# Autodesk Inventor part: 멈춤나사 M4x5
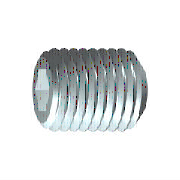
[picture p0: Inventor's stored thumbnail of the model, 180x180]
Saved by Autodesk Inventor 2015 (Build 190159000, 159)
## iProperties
IsCustomPart: 1
Created: 2012-02
Part Number: 멈춤나사 M4x5
Material: 강철, 연강
Description: 6각 소켓 머리 없는 멈춤 나사
Document SubType Name: Modeling
Standard: KS B 1028
Designer: mduedu
Standards Organization: KS
Language: ko-KR
Size Designation: 납작점M4x5
Categories: <MemberInstance><Categories><Category DisplayName="조임쇠" InternalName="e4da775c-781d-43d5-af7c-5136215cf5a6" Mnemonic="FSTN"><Category DisplayName="볼트" InternalN
Density: 1 g/cm^3
Appearance: 강철
Author: mduedu
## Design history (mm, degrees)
sketch "스케치1"
  geometry: L1 (0, 0)-(1.833, 0); L2 (5, 1.155)-(5, 2); L3 (5, 2)-(0, 2); L4 (5, 1.155)-(2.5, 1.155); L5 (2.5, 1.155)-(1.833, 0); L6 (0, -0.4)-(0, 2.4) reference; L7 (0, 2)-(0, 0)
  constraints: 13 end point, 3 parallel, 1 collinear, 1 perpendicular, 1 point on line
  dimensions: "d0" = 2.5 distance of L2.start L4.end (= INTI); "d1" = 60 deg angle of L5 L1; "d2" = 4 diameter of L3 L1 (= NND); "d3" = 2.3094 diameter of L4 L1 (= 1.1547 x SW); "d5" = 5 distance from line of L2 L3.end (= NLG)
revolve "본체" sketch "스케치1" stored, may be unused: angle "d6" = 90 deg
sketch "스케치2"
  geometry: L1 (-0.577, 1)-(0.577, 1); L2 (0.577, 1)-(1.155, 0); L3 (1.155, 0)-(0.577, -1); L4 (0.577, -1)-(-0.577, -1); L5 (-0.577, -1)-(-1.155, 0); L6 (-1.155, 0)-(-0.577, 1); A1 r 1.155 centre (0, 0) between (-0.577, 1) and (0.577, 1) reference; 2 further points
  constraints: 12 end point, 2 point on circle, 1 coincident, 1 horizontal, 11 other
extrude "슬롯" join sketch "스케치2" taper "d9" = 0 deg; stored distance "d21" = 10
workaxis "Work Axis1"
workplane "Work Plane1"
body "Solid1"
chamfer "모따기1" distance "d7" = 0.42941 (= -0.5 x GD1 + 0.5 x NND); stored, may be unused: angle "d8" = 45 deg (= FAWI), second distance "d29" = 0.42941 (= -0.5 x GD1 + 0.5 x NND)
feature "스레드" dims "d11" = 5 (= NLG), "d12" = 0
chamfer "모따기2" distance "d13" = 0.42941 (= -0.5 x GD1 + 0.5 x NND); stored, may be unused: angle "d14" = 45 deg (= FAWI), second distance "d30" = 0.42941 (= -0.5 x GD1 + 0.5 x NND)
other parameters: "NND" = 4 [user parameter; used in 5 equation terms], "NLG" = 5 [user parameter; used in 2 equation terms], "INTI" = 2.5 [user parameter; used in 1 equation term], "FAWI" = 45 deg [user parameter; used in 2 equation terms], "SW" = 2 [user parameter; used in 2 equation terms], "GD1" = 3.14117 (= THREADDIA - 1.2269 x PTC) [user parameter; used in 4 equation terms], "d4" = 0, "FAWI1" = 45 deg [user parameter], "d15" = 0, "d31" = 0, "GUL" = 0.42941 (= 0.61345 x PTC) [user parameter], "SPD" = 2.5 [user parameter], "TPU" = 14.28571 (computed from PTC) [user parameter], "TOA" = 30 deg [user parameter], "THREADDIA" = 4 [user parameter; used in 1 equation term], "PTC" = 0.7 [user parameter; used in 4 equation terms], "GAL" = 0.42941 (= 0.61345 x PTC) [user parameter], "E0" = 2.31 (= 1.155 x SW) [user parameter]
